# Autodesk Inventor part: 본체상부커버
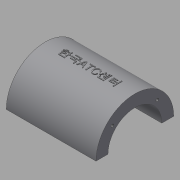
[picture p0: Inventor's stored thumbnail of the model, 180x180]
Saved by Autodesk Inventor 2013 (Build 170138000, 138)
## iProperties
Created: 2015-12
Part Number: 본체상부커버
Material: 일반
Document SubType Name: Modeling
Designer: mduedu
Density: 1 g/cm^3
Mass: 64.6353 g
Surface Area: 166.445 cm^2
Volume: 64.6353 cm^3
Author: mduedu
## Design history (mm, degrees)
sketch "스케치1"
  geometry: L1 (45, 40)-(-45, 40); L2 (-45, 40)-(-45, -40); L3 (-45, -40)-(45, -40); L4 (45, -40)-(45, 40); L5 (45, 40)-(-45, -40); L6 (-45, 40)-(45, -40); 2 further points
  constraints: 12 end point, 2 midpoint, 2 parallel, 1 coincident, 1 horizontal, 1 perpendicular, 3 other
  dimensions: "d0" = 90 distance of L2.end L3.end; "d2" = 80 distance of L1.end L2.end
extrude "돌출1" new body sketch "스케치1" distance "d3" = 10; taper "d4" = 0 deg
sketch "스케치2"
  geometry: C1 r 32.5 at (80, 0); 1 further point
  constraints: 1 centre point
  dimensions: "d5" = 65 diameter of C1; "d116" = 80 distance of point (0, 0) C1.centre
extrude "돌출2" join sketch "스케치2" stored distance "d7" = 75; taper "d8" = 0 deg
sketch "스케치3"
  geometry: L1 (-27.5, -20)-(27.5, -20); L2 (27.5, -20)-(27.5, 20); L3 (27.5, 20)-(-27.5, 20); L4 (-27.5, 20)-(-27.5, -20); L5 (-27.5, -20)-(27.5, 20); L6 (27.5, -20)-(-27.5, 20); 1 further point
  constraints: 12 end point, 2 midpoint, 2 parallel, 1 horizontal, 1 perpendicular
  dimensions: "d9" = 55 distance of L2.end L3.end; "d11" = 40 distance of L1.end L2.end
extrude "돌출3" new body sketch "스케치3" stored distance "d12" = 75; taper "d13" = 0 deg
fillet "모깎기1"
fillet "모깎기2"
feature "결합1"
  node "솔리드2"
sketch "스케치4"
  geometry: L1 (-37.5, 47.5)-(37.5, 47.5) reference; L2 (32.5, 47.5)-(40.208, 10); L3 (37.5, 47.5)-(37.5, 112.5) reference; L4 (60.208, 0)-(60.208, 10) reference; L5 (60.208, 10)-(-60.208, 10) reference; 1 further point
  constraints: 2 end point, 2 point on line
  dimensions: "d15" = 5 distance from line of L2.start L3; "d117" = 20 distance from line of L2.end L4
sketch "스케치5"
  geometry: L1 (10, 35.208)-(56.729, 22.687); L2 (0, 60.208)-(10, 60.208) reference; L3 (10, -60.208)-(10, 60.208) reference; 2 further points
  constraints: 2 end point, 1 point on line, 2 other
  dimensions: "d118" = 25 distance from line of L1.start L2; "d119" = 75 deg angle of L1 L3
feature "리브1" dims "d19" = 1, "d20" = 6, "d21" = 0, "d22" = 0, "d23" = 1, "d24" = 1
feature "리브2" dims "d25" = 1, "d26" = 6, "d27" = 0, "d28" = 0, "d29" = 1, "d30" = 1
fillet "모깎기4" dims "d31" = 2
fillet "모깎기5" dims "d32" = 2
fillet "모깎기6" dims "d33" = 2
sketch "스케치6"
  geometry: L1 (0, 0)-(-32.88, 32.88); L2 (0, 0)-(-46.5, 0); A1 r 46.5 centre (0, 0) between (-32.88, 32.88) and (-46.5, 0); 5 further points
  constraints: 4 end point, 2 coincident, 2 point on circle, 1 centre point, 1 horizontal, 5 other
  dimensions: "d120" = 93 diameter of A1; "d122" = 45 deg angle of L1 L2; "d126" = 360 deg dimension on point (0, 0) point (-32.88, 32.88) (derived)
hole "구멍1" sketch "스케치6" at (-32.88, 32.88), (-32.88, -32.88), (32.88, -32.88), (32.88, 32.88) diameter "d34" = 7; stored, may be unused: countersink angle "d38" = 90 deg, drill point angle "d40" = 118 deg; dims "d35" = 6, "d36" = 12, "d37" = 3, "d39" = 8
fillet "모깎기13" dims "d131" = 3
hole "구멍2" diameter "d44" = 45; stored, may be unused: countersink angle "d48" = 90 deg, drill point angle "d50" = 118 deg; dims "d42" = 10, "d43" = 10, "d45" = 6, "d46" = 4, "d47" = 2, "d49" = 8
sketch "스케치7" dims "d52" = 26.5
  geometry: L1 (0, 0)-(32.5, 0); L2 (0, 0)-(22.981, 22.981); A1 r 32.5 centre (0, 0) between (32.5, 0) and (22.981, 22.981) reference; 3 further points
  constraints: 4 end point, 2 point on circle, 1 coincident, 1 horizontal, 1 point on line, 3 other
  dimensions: "d51" = 45 deg angle of L2 L1
hole "구멍3" sketch "스케치7" at (18.738, 18.738) diameter "d54" = 2.459; stored, may be unused: countersink angle "d58" = 90 deg, drill point angle "d60" = 118 deg; dims "d55" = 8, "d56" = 4, "d57" = 2, "d59" = 10
sketch "스케치9"
  geometry: L1 (-75, -110)-(75, -110); L2 (75, -110)-(75, 0); L3 (75, 0)-(-75, 0); L4 (-75, 0)-(-75, -110); L5 (-60.208, -80)-(60.208, -80) reference; C1 r 32.5 at (0, 0) reference; 2 further points
  constraints: 8 end point, 2 parallel, 1 coincident, 1 horizontal, 1 midpoint, 1 perpendicular
  dimensions: "d148" = 30 distance between parallel lines of L5 L1; "d159" = 150 distance between parallel lines of L2 L4
extrude "돌출5" cut sketch "스케치9" stored distance "d73" = 0; taper "d74" = 0 deg
node "작업 평면3"
sketch "스케치17" dims "d2" = 80
  geometry: 2 further points
  constraints: 1 coincident, 1 other
feature "엠보싱1" sketch "스케치17" dims "d0" = 90, "d2" = 80, "d150" = 0.5, "d151" = 0
node "솔리드1"
mirror "대칭1"
mirror "대칭2"
pattern_circular "원형 패턴1" dims angle "d62" = 360 deg
mirror "대칭3"
